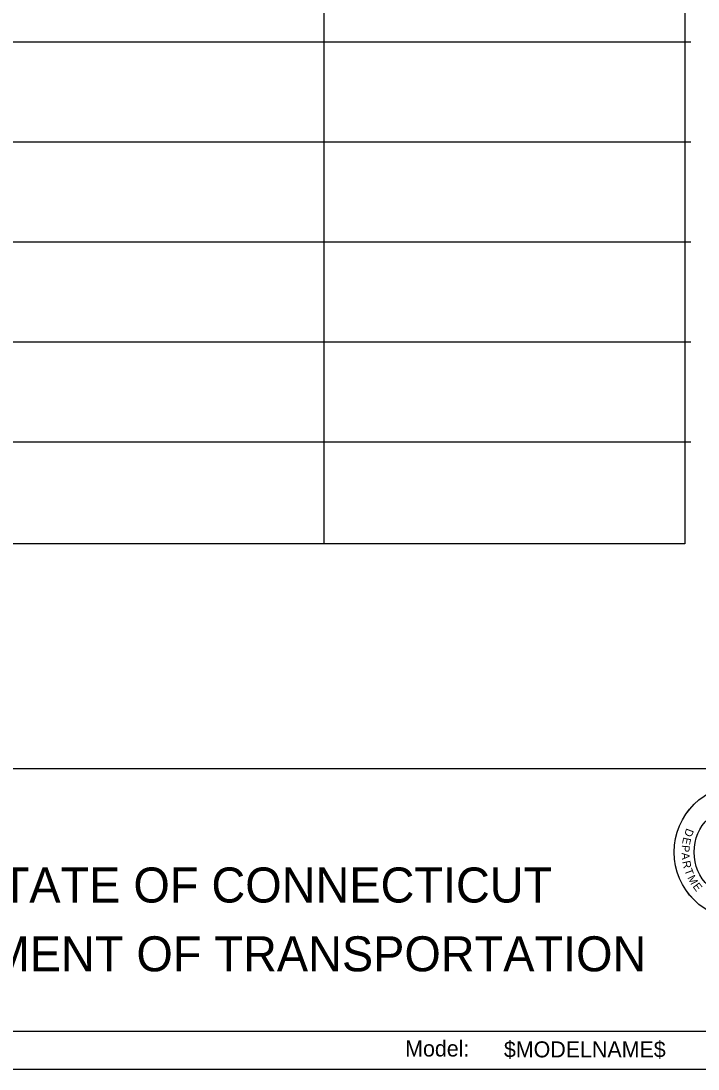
# Model space of a CAD drawing. Extents: x 0 to 5.28, y 0 to 1.73.
# Drawn here: x 1.0127 to 1.2947, y 0 to 0.4365 of the extents above; entities that cross this region are included whole.
import ezdxf

# ---------------------------------------------------------------- set-up
doc = ezdxf.new("R2010")
doc.units = 0
for name, color, linetype in [('CT_Border_Perimeter_Shape', 7, 'Continuous'), ('CT_Dimensions', 7, 'Continuous'), ('CT_Graphics', 7, 'Continuous'), ('CT_List_of _Standards', 7, 'Continuous'), ('CT_State_of_Connecticut_Text', 7, 'Continuous'), ('CT_Title_Block_Linework', 7, 'Continuous'), ('CT_Title_Block_Text', 7, 'Continuous')]:
    doc.layers.add(name, color=color, linetype=linetype)

msp = doc.modelspace()

# ---------------------------------------------------------------- linework, layer by layer
at = {"layer": 'CT_Border_Perimeter_Shape'}
msp.add_lwpolyline([(0, 0), (2.64583, 0), (2.64583, 1.72917), (0, 1.72917)], close=True, dxfattribs=at)
at = {"layer": 'CT_Dimensions'}
msp.add_lwpolyline([(0.02045, 1.66667), (1.28923, 1.66667), (1.28923, 0.21875), (0.02045, 0.21875)], close=True, dxfattribs=at)
msp.add_lwpolyline([(0.02045, 1.66667), (1.28923, 1.66667), (1.28923, 0.21875), (0.02045, 0.21875)], close=True, dxfattribs=at)
at = {"layer": 'CT_Graphics'}
for centre, major_axis in [((1.31295, 0.09033), (0, 0.02818)), ((1.31296, 0.09033), (0, 0.02818)), ((1.31295, 0.09033), (0, 0.01989))]:
    msp.add_ellipse(centre, major_axis=major_axis, ratio=0.99999, dxfattribs=at)
at = {"layer": 'CT_List_of _Standards'}
for p, q in [((1.1388, 1.66667), (1.1388, 0.21875)), ((0.02045, 0.42783), (1.29167, 0.42783)), ((0.02045, 0.42783), (1.29167, 0.42783)), ((0.02045, 0.38616), (1.29167, 0.38616)), ((0.02045, 0.38616), (1.29167, 0.38616)), ((0.02045, 0.38616), (1.29167, 0.38616)), ((0.02045, 0.3445), (1.29167, 0.3445)), ((0.02045, 0.3445), (1.29167, 0.3445)), ((0.02045, 0.30283), (1.29167, 0.30283)), ((0.02045, 0.30283), (1.29167, 0.30283)), ((0.02045, 0.26116), (1.29167, 0.26116)), ((0.02045, 0.26116), (1.29167, 0.26116))]:
    msp.add_line(p, q, dxfattribs=at)
at = {"layer": 'CT_Title_Block_Linework'}
for p, q in [((2.64583, 0.125), (0, 0.125)), ((1.35804, 0.01563), (0.90822, 0.01563))]:
    msp.add_line(p, q, dxfattribs=at)

# ---------------------------------------------------------------- texts
at = {"layer": 'CT_Graphics'}
for s, rotation, p in [('E', 257.9978, (1.28863, 0.09673)), ('D', 248.9249, (1.28995, 0.10049)), ('P', 265.8361, (1.28799, 0.09336)), ('A', 273.4128, (1.28781, 0.09004)), ('R', 281.7094, (1.28811, 0.08641)), ('T', 290.1103, (1.28895, 0.08283)), ('M', 297.8049, (1.29017, 0.07968)), ('E', 307.5238, (1.2923, 0.07599))]:
    msp.add_text(s, height=0.00333, rotation=rotation, dxfattribs=at).set_placement(p)
at = {"layer": 'CT_State_of_Connecticut_Text'}
for s, p in [('STATE OF CONNECTICUT', (0.99129, 0.06935)), ('DEPARTMENT OF TRANSPORTATION', (0.92104, 0.04069))]:
    msp.add_text(s, height=0.0145833, dxfattribs=at).set_placement(p)
at = {"layer": 'CT_Title_Block_Text'}
for s, height, p in [('Model:', 0.006667, (1.17273, 0.00522)), ('$MODELNAME$', 0.0066667, (1.21385, 0.00486))]:
    msp.add_text(s, height=height, dxfattribs=at).set_placement(p)

doc.saveas('drawing.dxf')
